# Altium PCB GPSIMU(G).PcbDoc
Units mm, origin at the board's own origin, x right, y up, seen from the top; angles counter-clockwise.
Board outline 35 x 59.99 mm, 2 copper layers (Top Layer, Bottom Layer); 106 components, 112 nets, 390 pads, 86 vias.
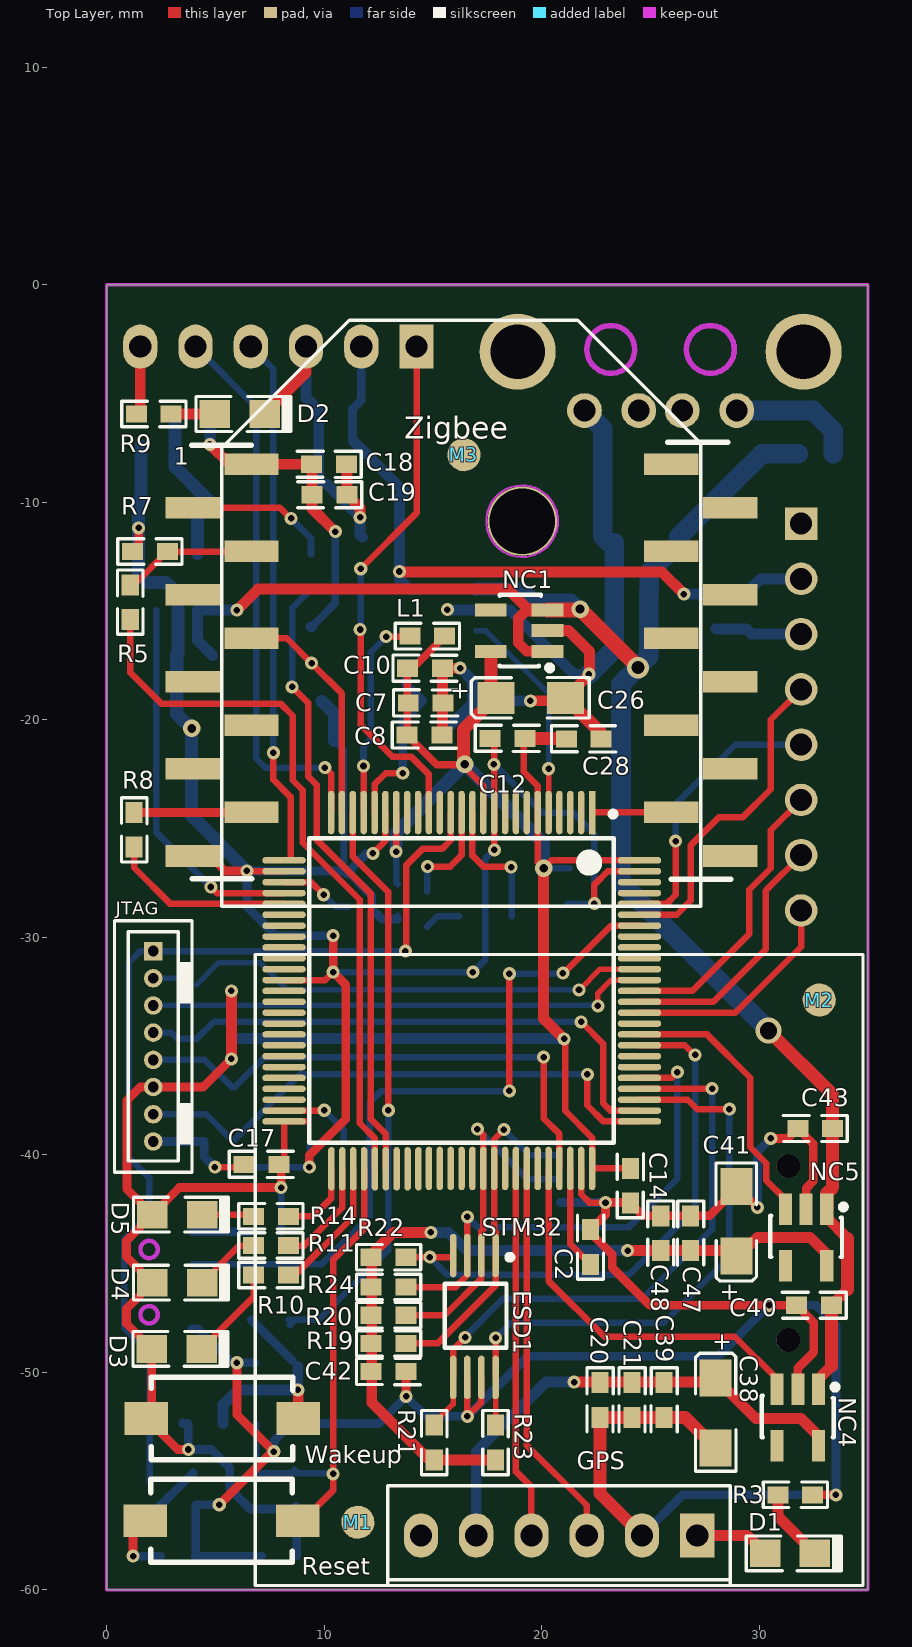
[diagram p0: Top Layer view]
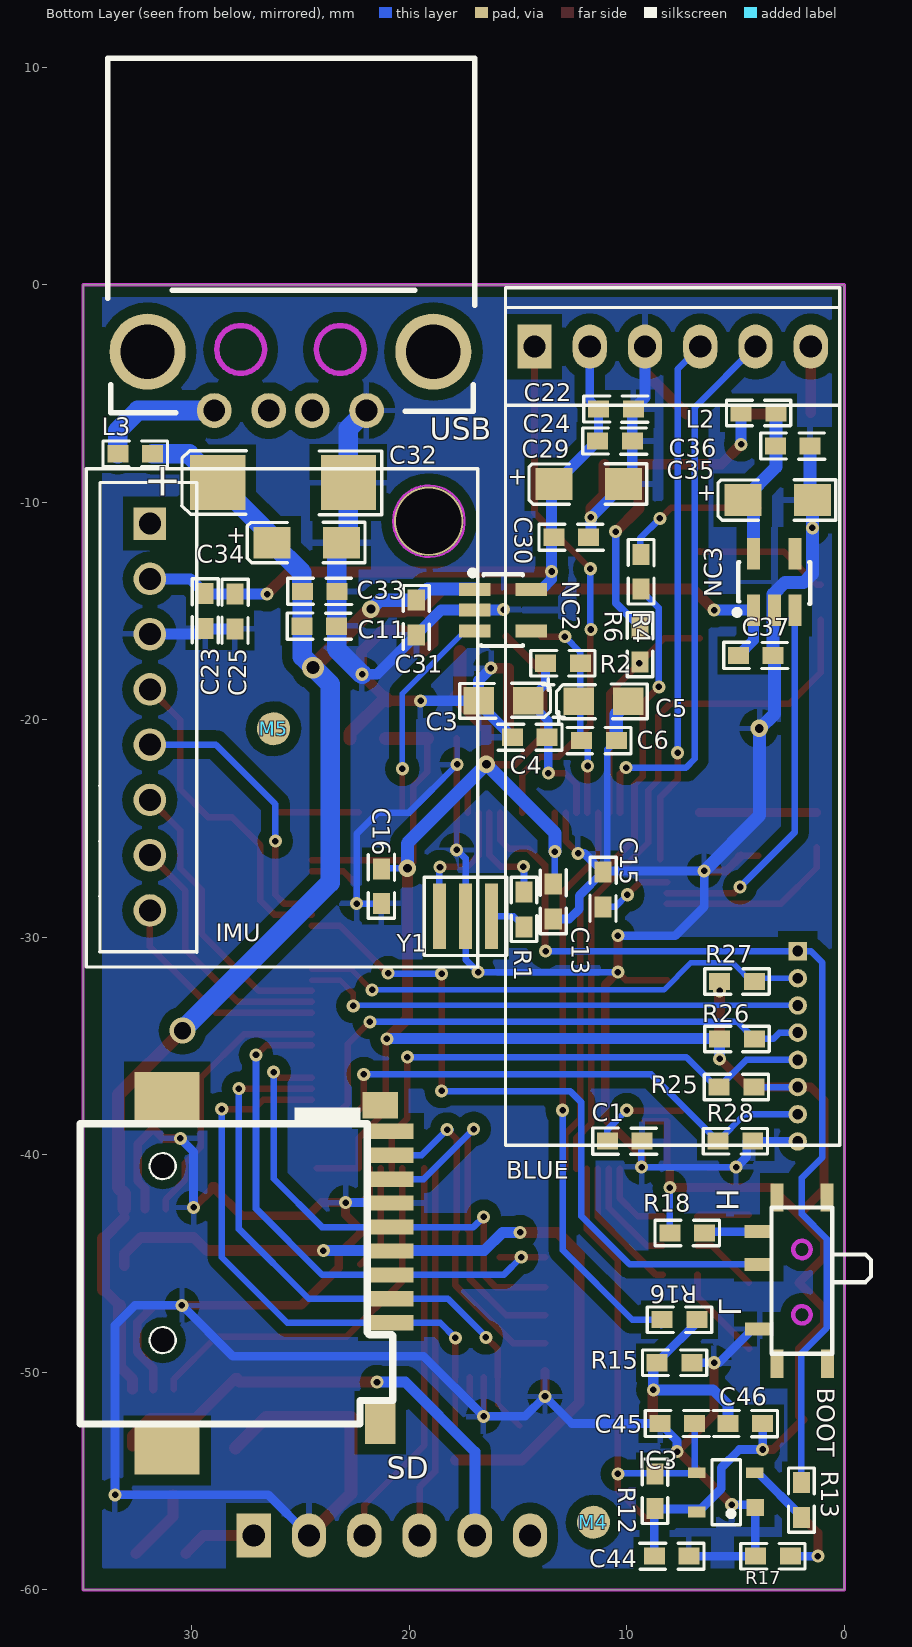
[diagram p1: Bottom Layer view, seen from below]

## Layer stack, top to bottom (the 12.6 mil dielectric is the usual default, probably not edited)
Top Layer: signal copper 0.0356
Dielectric: core 0.32, FR-4, Dk 4.8
Bottom Layer: signal copper 0.0356

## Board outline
0,0 35.001,0 35.001,-59.995 0,-59.995

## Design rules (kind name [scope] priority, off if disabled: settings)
Clearance [All] p1: gap=0.5
PolygonConnect [All] p1: connectstyle=Relief reliefconductorwidth=0.254 reliefentries=4 polygonreliefangle="90 Angle"
RoutingVias [All] p1: holewidth=0.711 width=1.27 viastyle="Through Hole" minholewidth=0.711 minwidth=1.27 maxholewidth=0.711 maxwidth=1.27
SilkscreenOverComponentPads [All] p1: minsilkscreentomaskgap=0.254
SolderMaskExpansion [All] p1: expansion=0.102
Width [All] p1: maxlimit=2.54 minlimit=0.2 preferedwidth=0.254
27 further rules are at their usual default settings.

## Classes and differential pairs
component class CPU_STM32F4: C1 C2 C3 C4 C5 C6 C7 C8 C10 C12 C13 C14 C15 C16 C17 L1 R1 R2 STM32 Y1
component class IMU_GPS: BLUE Bluetooth C18 C19 C20 C21 C22 C23 C24 C25 D1 D2 GPS IC2 IMU L2 P1 P2 P3 R3 R4 R5 R6 R7 R8 R9 Zigbee
component class IMU_POW: C11 C26 C27 C28 C29 C30 C31 C32 C33 C34 C35 C36 C37 C38 C39 C40 C41 C42 C43 L3 NC1 NC2 NC3 NC4 NC5
component class IMU_REIO: BOOT C44 C45 C46 D3 D4 D5 IC3 M1 M2 M3 M4 M5 M6 R10 R11 R12 R13 R14 R15 R16 R17 R18 Reset S1 S2 Wakeup
component class IMU_SD: C47 C48 ESD1 J1 JTAG R19 R20 R21 R22 R23 R24 R25 R26 R27 R28 SD

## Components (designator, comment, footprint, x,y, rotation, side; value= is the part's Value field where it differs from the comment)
BLUE "蓝牙模块" HC-06(35.7*15.2MM) 14.249,-2.845 r180 bottom locked (schematic designator P3)
BOOT "SW-SPDT" SW-PD-5(10) 1.829,-49.149 r90 bottom locked (schematic designator S3)
C1 "1uF" 0603 9.296,-39.37 r0 bottom
C2 "1uF" 0603 22.25,-43.434 r270 top
C3 "1uF/16V" C-M(0805) 14.91,-20.269 r0 bottom
C4 "100n" 0603 15.265,-20.803 r180 bottom
C5 "1uF/16V" C-M(0805) 11.836,-18.009 r180 bottom
C6 "100n" 0603 12.09,-20.955 r180 bottom
C7 "100n" 0603 15.469,-19.228 r180 top
C8 "100n" 0603 15.418,-20.701 r180 top
C10 "100n" 0603 15.443,-17.628 r180 top
C11 "100n" 0603 23.343,-15.697 r0 bottom
C12 "100n" 0603 19.228,-20.853 r180 top
C13 "100n" 0603 13.386,-27.559 r270 bottom
C14 "100n" 0603 24.079,-40.615 r270 top
C15 "100n" 0603 11.1,-28.6 r90 bottom
C16 "100n" 0603 21.285,-26.848 r270 bottom
C17 "100n" 0603 7.925,-40.437 r180 top
C18 "100n" 0603 9.423,-8.255 r0 top
C19 "100n" 0603 9.449,-9.652 r0 top
C20 "100n" 0603 22.682,-52.07 r90 top
C21 "100n" 0603 24.155,-52.07 r90 top
C22 "100n" 0603 9.703,-5.715 r0 bottom
C23 "100n" 0603 29.388,-15.799 r90 bottom
C24 "100n" 0603 9.754,-7.188 r0 bottom
C25 "100n" 0603 28.016,-15.824 r90 bottom
C26 "4u7/10V" C-A(3216-18) 17.907,-18.999 r0 top
C28 "100n" 0603 22.733,-20.879 r180 top
C29 "4u7/10V" C-A(3216-18) 13.36,-9.169 r180 bottom
C30 "100n" 0603 11.76,-11.608 r0 bottom
C31 "100n" 0603 19.685,-16.104 r90 bottom
C32 "220u/10V" C-C(6032-28) 28.804,-9.093 r180 bottom
C33 "100n" 0603 23.317,-14.097 r0 bottom
C34 "4u7/10V" C-A(3216-18) 26.314,-11.862 r180 bottom
C35 "4u7/10V" C-A(3216-18) 4.674,-9.906 r180 bottom
C36 "100n" 0603 1.575,-7.417 r0 bottom
C37 "100n" 0603 3.277,-17.043 r0 bottom
C38 "4u7/10V" C-A(3216-18) 27.991,-50.267 r270 top
C39 "100n" 0603 25.629,-52.07 r90 top
C40 "100n" 0603 31.725,-46.914 r0 top
C41 "4u7/10V" C-A(3216-18) 28.956,-44.653 r90 top
C42 "100n" 0603 13.767,-49.962 r180 top
C43 "100n" 0603 31.775,-38.786 r0 top
C44 "100n" 0603 8.738,-58.445 r180 bottom
C45 "100n" 0603 6.883,-52.349 r0 bottom
C46 "100n" 0603 5.359,-52.349 r180 bottom
C47 "100n" 0603 26.848,-44.399 r90 top
C48 "100n" 0603 25.476,-44.399 r90 top
D1 "LED red" D0805 30.277,-58.318 r0 top
D2 "LED red" D0805 4.978,-5.944 r0 top
D3 "LED red" D0805 2.083,-48.92 r0 top
D4 "LED red" D0805 2.108,-45.872 r0 top
D5 "LED red" D0805 2.108,-42.748 r0 top
ESD1 "PESD5V0L6UAS" MSOP-8 17.882,-44.628 r270 top
GPS "GPS" "GPS 28*28MM" 27.635,-48.565 r270 top locked (schematic designator P1)
IC3 "MAX6315US26D2-T" TO-253 4.877,-54.991 r0 top
IMU "IMU" GY-85 24.232,-18.567 r180 bottom locked (schematic designator P2)
JTAG "CON-SIP8-2.0" PLUG1.27-8P 2.261,-33.477 r270 top (schematic designator P4)
L1 "22uH" 0603 15.545,-16.154 r180 top
L2 "22uH" 0603 3.15,-5.893 r0 bottom
L3 "22uH" 0603 33.401,-7.772 r180 bottom
M1 "CON-PAD" BAD_MARK 11.557,-56.871 r0 top
M2 "CON-PAD" BAD_MARK 32.766,-32.868 r0 top
M3 "CON-PAD" BAD_MARK 16.434,-7.798 r0 top
M4 "CON-PAD" BAD_MARK 11.532,-56.871 r180 bottom
M5 "CON-PAD" BAD_MARK 26.238,-20.396 r180 bottom
NC1 "NCP603SN330T1G" TSSOP-5 19.406,-16.256 r180 top
NC2 "NCP603SN330T1G" TSSOP-5 16.129,-14.605 r180 bottom
NC3 "NCP603SN330T1G" TSSOP-5 3.581,-14.097 r90 bottom
NC4 "NCP603SN330T1G" TSSOP-5 32.131,-51.638 r270 top
NC5 "NCP603SN330T1G" TSSOP-5 32.512,-43.358 r270 top
R1 "390" 0603 14.732,-29.515 r90 bottom
R2 "47" 0603 12.141,-17.399 r0 bottom
R3 "1K" 0603 32.461,-55.626 r180 top
R4 "1K" 0603 9.347,-12.395 r270 bottom
R5 "10K" 0603 1.092,-13.792 r270 top
R6 "10K" 0603 9.398,-15.748 r270 bottom
R7 "15K" 0603 2.794,-12.268 r180 top
R8 "1K" 0603 1.27,-24.257 r270 top
R9 "1K" 0603 2.972,-5.944 r180 top
R10 "1K" 0603 6.756,-45.517 r0 top
R11 "1K" 0603 6.756,-44.171 r0 top
R12 "47K" 0603 8.712,-54.661 r270 bottom
R13 "3.9K" 0603 1.981,-56.667 r90 bottom
R14 "1K" 0603 6.756,-42.824 r0 top
R15 "47K" 0603 7.01,-49.555 r0 bottom
R16 "1K" 0603 6.782,-47.574 r0 bottom
R17 "10K" 0603 4.089,-58.445 r180 bottom
R18 "10K" 0603 6.426,-43.586 r0 bottom
R19 "10K" 0603 13.767,-48.666 r180 top
R20 "10K" 0603 13.767,-47.371 r180 top
R21 "10K" 0603 15.062,-52.426 r270 top
R22 "10K" 0603 13.767,-44.704 r180 top
R23 "10K" 0603 17.882,-52.426 r270 top
R24 "10K" 0603 13.767,-46.076 r180 top
R25 "3.9K" 0603 5.766,-36.881 r180 bottom
R26 "3.9K" 0603 4.14,-34.671 r0 bottom
R27 "3.9K" 0603 4.14,-32.029 r0 bottom
R28 "3.9K" 0603 4.216,-39.37 r0 bottom
Reset "Manual Pushbutton" KEY-6*4 1.778,-56.82 r90 top locked (schematic designator S1)
SD "SD_CARD_SLOT" mini-SD 21.641,-46.076 r0 bottom locked (schematic designator J1)
STM32 "STM32F40x-VG (LQFP100)" "LQFP100 (14*14)" 17.602,-31.013 r270 top locked (schematic designator IC1)
USB "车载转换头" SMT-USB 18.898,-3.073 r0 bottom (schematic designator J(USB)2)
Wakeup "Manual Pushbutton" KEY-6*4 8.814,-52.121 r270 top locked (schematic designator S2)
Y1 "8Mhz" XT-3.2*1.5 18.618,-29.032 r180 bottom
Zigbee "XBEE PRO(802.15.4)/" SMT-Zigbee-2.0 3.962,-8.255 r0 top locked (schematic designator IC2)

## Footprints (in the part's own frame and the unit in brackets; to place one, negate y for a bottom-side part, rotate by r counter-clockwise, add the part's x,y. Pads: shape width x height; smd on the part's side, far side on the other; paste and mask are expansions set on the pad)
0603 [mil]
  rect 38x31 smd: 1(0,0) 2(63,0)
  silkscreen extent -26,-24 90,24
BAD_MARK [mil] "MARK 点"
  round 60 smd mask+29.53: 0(-0.25,-0.63)
C-A(3216-18) [mm]
  rect 1.7x1.47 smd: 1(0,0) 2(3.2,0)
  silkscreen extent -1.14,-0.92 4.28,0.94
C-C(6032-28) [mm]
  rect 2.54x2.54 smd: 1(0,0) 2(6,0)
  silkscreen extent -1.66,-1.47 7.53,1.45
C-M(0805) [mil] "钽电容"
  rect 55.12x50 smd: 1(-15,-45) 2(75,-45)
  silkscreen extent -80,-76 109,-5
D0805 [mm]
  rect 1.4x1.27 smd: A(0,0) K(2.286,0)
  silkscreen extent -0.87,-0.81 3.5,0.8
"GPS 28*28MM" [mil] "BS-280  GPS接收"
  rect 80x62 hole 40: 1(351.73,-19)
  oval 80x62 hole 40: 2(351.73,-119) 3(351.73,-219) 4(351.73,-319) 5(351.73,-419) 6(351.73,-519)
  silkscreen extent -700,-819 442,281
GY-85 [mm]
  round 3.2 hole 3: 0(5.12,7.698)
  rect 1.5x1.5 hole 1.016: 1(-7.697,7.584)
  round 1.5 hole 1.016: 2(-7.697,5.044) 3(-7.697,2.504) 4(-7.697,-0.036) 5(-7.697,-2.576) 6(-7.697,-5.116) 7(-7.697,-7.656) 8(-7.697,-10.196)
  silkscreen extent -10.63,-12.8 7.37,10.11
HC-06(35.7*15.2MM) [mil] "蓝牙模块"
  rect 62x80 hole 40: 1(0,0)
  oval 62x80 hole 40: 2(100,0) 3(200,0) 4(300,0) 5(400,0) 6(500,0)
  silkscreen extent -52,-1446 552,106
KEY-6*4 [mm] "2PIN"
  rect 1.5x2 smd: 1(0,0) 2(0,-7)
  silkscreen extent -1.9,-6.75 1.9,-0.25
"LQFP100 (14*14)" [mm]
  rect 2x0.3 smd: 1(-6.751,4.716)
  oval 2x0.3 smd: 2(-6.751,4.216) 3(-6.751,3.716) 4(-6.751,3.216) 5(-6.751,2.716) 6(-6.751,2.216) 7(-6.751,1.716) 8(-6.751,1.216) 9(-6.751,0.716) 10(-6.751,0.216) 11(-6.751,-0.284) 12(-6.751,-0.784) 13(-6.751,-1.284) 14(-6.751,-1.784) 15(-6.751,-2.284) 16(-6.751,-2.784) 17(-6.751,-3.284) 18(-6.751,-3.784) 19(-6.751,-4.284) 20(-6.751,-4.784) 21(-6.751,-5.284) 22(-6.751,-5.784) 23(-6.751,-6.284) 24(-6.751,-6.784) 25(-6.751,-7.284) 51(9.629,-7.264) 52(9.629,-6.764) 53(9.629,-6.264) 54(9.629,-5.764) 55(9.629,-5.264) 56(9.629,-4.764) 57(9.629,-4.264) 58(9.629,-3.764) 59(9.629,-3.264) 60(9.609,-2.784) 61(9.609,-2.284) 62(9.609,-1.784) 63(9.609,-1.284) 64(9.609,-0.784) 65(9.609,-0.284) 66(9.609,0.216) 67(9.609,0.716) 68(9.609,1.216) 69(9.609,1.716) 70(9.609,2.216) 71(9.609,2.716) 72(9.609,3.216) 73(9.609,3.716) 74(9.609,4.216) 75(9.609,4.716)
  oval 0.3x2 smd: 26(-4.551,-9.444) 27(-4.051,-9.444) 28(-3.551,-9.444) 29(-3.051,-9.444) 30(-2.551,-9.444) 31(-2.051,-9.444) 32(-1.551,-9.444) 33(-1.051,-9.444) 34(-0.551,-9.444) 35(-0.051,-9.444) 36(0.449,-9.444) 37(0.949,-9.444) 38(1.449,-9.444) 39(1.949,-9.444) 40(2.449,-9.444) 41(2.949,-9.444) 42(3.449,-9.444) 43(3.949,-9.444) 44(4.449,-9.444) 45(4.949,-9.444) 46(5.449,-9.444) 47(5.949,-9.444) 48(6.449,-9.444) 49(6.949,-9.444) 50(7.449,-9.444) 76(7.449,6.896) 77(6.949,6.896) 78(6.449,6.896) 79(5.949,6.896) 80(5.449,6.896) 81(4.949,6.896) 82(4.449,6.896) 83(3.949,6.896) 84(3.449,6.896) 85(2.949,6.896) 86(2.449,6.896) 87(1.949,6.896) 88(1.449,6.896) 89(0.949,6.896) 90(0.449,6.896) 91(-0.051,6.896) 92(-0.551,6.896) 93(-1.051,6.896) 94(-1.551,6.896) 95(-2.051,6.896) 96(-2.551,6.896) 97(-3.051,6.896) 98(-3.551,6.896) 99(-4.051,6.896) 100(-4.551,6.896)
  silkscreen extent -6.8,-8.28 8.43,5.8
mini-SD [mm]
  rect 1.629x1.225 smd: 0(-0.301,-8.358)
  rect 1.4x1.93 smd: 0(-0.301,6.242)
  rect 3x2.2 smd: 0(9.5,-8.778) 0(9.5,7.52)
  rect 2.057x0.7 smd: 1(-0.801,1.642) 2(-0.801,0.542) 3(-0.801,-0.558) 4(-0.801,-1.658) 5(-0.801,-2.758) 6(-0.801,-3.858) 7(-0.801,-4.958) 8(-0.801,-6.058) 9(-0.801,-7.158)
  round 1.1 hole 1.1: ""(9.699,-5.558) ""(9.699,2.442)
  silkscreen extent -0.88,-8.26 13.5,6.29
MSOP-8 [mm]
  oval 2x0.3 smd: 1(0,0) 2(0,-0.65) 3(0,-1.3) 4(0,-1.95) 5(5.6,-1.95) 6(5.6,-1.3) 7(5.6,-0.65) 8(5.6,0)
  silkscreen extent -0.05,-2.34 4.24,0.79
PLUG1.27-8P [mm]
  rect 0.85x0.85 hole 0.5: 1(-2.845,-0.114)
  round 0.85 hole 0.5: 2(-1.595,-0.114) 3(-0.345,-0.114) 4(0.905,-0.114) 5(2.155,-0.114) 6(3.405,-0.114) 7(4.655,-0.114) 8(5.905,-0.114)
  silkscreen extent -4.24,-1.89 7.32,1.66
SMT-USB [mm]
  round 3.5 hole 2.5: 0(0,0) 0(13.14,0)
  round 1.6 hole 1: 1(3.07,2.71) 2(5.57,2.71) 3(7.57,2.71) 4(10.07,2.71)
  Keep-Out Layer circle w0.254: c4.28,-0.1 r1.1
  Keep-Out Layer circle w0.254: c8.86,-0.1 r1.1
  silkscreen extent -1.89,-13.49 14.97,2.81
SMT-Zigbee-2.0 [mm] "2.0MM"
  rect 2.5x1 smd: 1(2.7,0) 2(0,-2) 3(2.7,-4) 4(0,-6) 5(2.7,-8) 6(0,-10) 7(2.7,-12) 8(0,-14) 9(2.7,-16) 10(0,-18) 11(24.7,-18) 12(22,-16) 13(24.7,-14) 14(22,-12) 15(24.7,-10) 16(22,-8) 17(24.7,-6) 18(22,-4) 19(24.7,-2) 20(22,0)
  silkscreen extent -0.05,-20.32 24.74,6.63
SW-PD-5(10) [mm]
  rect 1.3x0.6 smd: 0(-0.457,-1.041) 0(-0.457,1.27) 0(7.188,-1.016) 0(7.188,1.27)
  rect 0.6x1.3 smd: 1(1.143,2.083) 2(4.118,2.108) 3(5.618,2.108)
  Keep-Out Layer circle w0.2: c4.8,0.127 r0.4
  Keep-Out Layer circle w0.2: c1.8,0.127 r0.4
  silkscreen extent 0,-3.05 6.73,1.52
TO-253 [mm]
  rect 0.8x0.8 smd far side: 1(-0.781,-1.219)
  rect 0.8x0.5 smd far side: 2(-0.761,0.381) 3(1.919,0.381) 4(1.919,-1.419)
TSSOP-5 [mm]
  rect 1.45x0.6 smd: 1(-0.864,0.595) 2(-0.864,-0.355) 3(-0.864,-1.305) 4(1.736,-1.305) 5(1.736,0.595)
  silkscreen extent -1.09,-2 1.34,1.48
XT-3.2*1.5 [mm] "3.2*1.3*0.4mm"
  rect 0.6x3 smd: 1(0,0) 2(1.2,0) 3(2.4,0)
  silkscreen extent -0.7,-1.8 3.1,1.8

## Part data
BLUE: library part CON-SIP6-2.54, "单排针6PIN"
BOOT: "SPDT Subminiature Toggle Switch, Right Angle Mounting, Vertical Actuation"
C1 C2 C4 C6 C7 C8 C10 C11 C12 C13 C14 C15 C16 C17 C44 C45 C46: library part Cap, "TANTAMOUNT? 595D Vishay Sprague,50V,22.5mOhm"
C3 C5 C26 C29 C34 C35 C38 C41: library part C-A(3216-18)
C18 C19 C47 C48: library part Cap, "Capacitor"
C20 C21 C22 C23 C24 C25 C28 C31 C37 C40 C43: library part C-SMD
C30 C36 C39 C42: library part "Cap Semi", "Capacitor (Semiconductor SIM Model)"
C32: library part C-RB.1
C33: library part C-SMD电容
D1 D2 D3 D4 D5: library part diode-LED, "LED"
ESD1: library part PESD5V0L6U
GPS: library part CON6-2.54, "(栅)围栏式立(卧)6PIN"
IC3: library part "MAX 6468", "MAX 6468XS16D3 Reset and Supervisory Circuit"
IMU: library part CON8-2.54, "(栅)围栏式立(卧)8PIN"
JTAG: "单排针8PIN"
L1: library part Inductor, "fcm1608-0603"
L2: library part L-
L3: library part INDUCTOR
NC1 NC2 NC3 NC4 NC5: library part NCP551
R1 R2 R4 R5 R6 R7 R8 R10 R11 R12 R13 R14 R15 R16 R17 R18 R19 R20 R21 R22 R23 R24: library part Res3, "Resistor"
R3 R9: library part R-0603, "0603(SMD)"
R25 R26 R27 R28: library part R-0805, "0805(SMD)"
Reset Wakeup: library part 微动开关
STM32: library part STM32F40x-VG
USB: library part CON-USB1, "USB"
Y1: library part CRYSTAL-X3, "3PIN"
Zigbee: library part "XBEE PRO(802.15.4)"

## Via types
v1: diameter 0.6, hole 0.3, Top Layer to Bottom Layer, 80 vias
v2: diameter 0.8, hole 0.4, Top Layer to Bottom Layer, 4 vias
v3: diameter 1.2, hole 0.8, Top Layer to Bottom Layer, 1 vias
v4: diameter 1, hole 0.6, Top Layer to Bottom Layer, 1 vias

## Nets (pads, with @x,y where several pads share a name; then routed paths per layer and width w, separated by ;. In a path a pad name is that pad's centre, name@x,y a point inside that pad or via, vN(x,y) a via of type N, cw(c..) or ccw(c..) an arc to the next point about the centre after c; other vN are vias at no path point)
"BOOT0 (VPP)": BOOT.2 STM32.94 | length 34.8
  Top Layer w0.3: v1@18.517,-37.084 v1(18.517,-37.059) v1(18.517,-31.674) ; v1@20.98,-31.674 23.192,-29.462 STM32.94
  Bottom Layer w0.3: BOOT.2 7.569,-45.031 ; 8.613,-45.031 7.569,-45.031 ; 13.945,-37.084 13.437,-37.084 ; v1@18.491,-31.674 v1(18.517,-31.674) v1@20.98,-31.674 ; v1(18.517,-37.059) 18.491,-37.084 13.437,-37.084 ; 7.569,-45.031 9.881,-45.031 12.09,-42.822 12.09,-37.592 12.598,-37.084 13.437,-37.084
  other v1: 20.98,-31.648
CAR_5V: C11.2 C31.2 C32.1 C33.2 C34.1 C37.2 C40.2 C43.2 L3.2 NC1.1 NC1.3 NC2.1 NC3.1 NC4.1 NC5.1 | length 85.1
  Top Layer w0.5: v1(5.994,-14.961) 6.96,-13.995 18.452,-13.995 19.314,-14.857 19.314,-14.951 18.923,-15.342 18.923,-16.459 19.315,-16.851 NC1.1 ; NC4.1 32.726,-50.307 33.325,-49.708 ; NC5.1@33.107,-42.886 34.061,-43.84 ; C40.2 34.061,-46.177
  Top Layer w0.6: 19.314,-14.951 NC1.3 ; v3(30.429,-34.29) 33.376,-37.236 C43.2 33.376,-41.504 33.107,-41.772 NC5.1 ; 33.325,-49.708 C40.2 ; 34.061,-46.177 34.061,-43.84
  Top Layer w0.7: NC1.3 21.809,-14.951 v4@24.473,-17.615
  Bottom Layer w0.5: C37.2 4.176,-16.343 NC3.1 v1(5.994,-14.961) ; NC2.1@16.916,-13.995 NC2.1@17.008,-13.995
  Bottom Layer w0.6: NC2.1 17.008,-13.995 19.177,-13.995 C31.2 21.361,-14.503 v2(21.768,-14.91)
  Bottom Layer w0.9: C33.2 24.917,-17.094 23.647,-18.364 23.647,-27.483 v3@30.442,-34.277 ; C33.2@24.943,-14.097 24.943,-13.233 C34.1 26.314,-11.582 C32.1 30.124,-7.772 L3.2
  other v4: 24.435,-17.602
GND: BLUE.3 BOOT.1 C1.1 C2.1 C3.2 C4.1 C5.2 C6.2 C7.1 C8.1 C10.1 C11.1 C12.2 C13.2 C14.2 C15.2 C16.2 C17.2 C18.2 C19.2 C20.1 C21.1 C22.1 C23.1 C24.1 C25.1 C26.2 C28.1 C29.2 C30.1 C31.1 C32.2 C33.1 C34.2 C35.2 C36.1 C37.1 C38.2 C39.1 C40.1 C41.2 C42.1 C43.1 C44.2 C45.2 C47.2 C48.2 D2.K ESD1.6 ESD1.7 GPS.2 IC3.1 IMU.3 JTAG.8 NC1.2 NC2.2 NC3.2 NC4.2 NC5.2 R3.1 R7.2 R15.1 R17.1 R28.1 SD.6 STM32.10 STM32.20 STM32.27 STM32.37 STM32.74 STM32.99 USB.1 Y1.2 Zigbee.10 | length 294.1
  Top Layer w0.3: Zigbee.10 4.75,-26.255 Zigbee.10@4.894,-26.255 ; v1(4.978,-40.564) C17.2@6.248,-40.564 ; v1@6.452,-26.962 STM32.27 ; STM32.37 10.049,-31.962 v1(10.414,-31.598) ; v1(12.243,-26.137) 12.818,-25.561 STM32.20 ; v1@16.582,-52.024 v1(16.586,-52.019) 17.232,-51.374 ESD1.7 ; v1@16.582,-52.019 ESD1.6 ; C12.2@17.818,-20.853 STM32.10 17.818,-25.972 v1(17.831,-25.984) ; STM32.74 21.818,-41.808 22.199,-42.189 v1@22.885,-42.189 ; v1(22.428,-28.448) 22.428,-27.572 23.038,-26.962 STM32.99
  Top Layer w0.4: R7.2@1.473,-12.268 v1(1.473,-11.176) ; Zigbee.10@4.75,-26.255 5.444,-26.949 v1(6.452,-26.949) ; v1(5.182,-56.083) 7.62,-53.645 v1(7.696,-53.645) 5.994,-51.943 v1(5.994,-49.555) ; v1(9.322,-40.564) 9.322,-40.031 10.998,-38.355 10.998,-32.182 v1(10.414,-31.598) v1(10.414,-29.921) ; v1@13.767,-51.079 C42.1 ; v1@22.885,-42.189 v1(22.936,-42.189) ; C14.2@24.054,-42.189 v1(22.936,-42.189) ; C14.2 24.663,-42.799 C48.2 C47.2 27.712,-42.799 C41.2@29.007,-41.504 ; C41.2 C41.2@29.007,-41.504 ; C41.2@29.058,-41.453 C41.2@29.007,-41.504 ; v1(29.921,-42.418) C41.2@29.007,-41.504 ; v1(30.455,-46.914) 24.968,-46.914 23.241,-45.187 23.241,-44.583 22.25,-43.592 C2.1 22.936,-42.748 v1(22.936,-42.189) ; v1@30.48,-46.914 C40.1 32.512,-47.701 32.512,-49.073 31.776,-49.809 NC4.2 ; v1(30.531,-39.243) 31.318,-39.243 C43.1 32.487,-39.497 32.487,-41.199 32.157,-41.528 NC5.2 ; R3.1 v1(33.528,-55.626) v1@33.579,-55.626
  Top Layer w0.5: D2.K 9.169,-4.039 BLUE.3 ; C18.2 11.049,-8.28 C19.2 11.659,-10.262 v1(11.659,-10.693) ; C8.1@15.443,-20.676 C10.1 v1(16.256,-17.628) ; v1(19.482,-19.126) C26.2@20.98,-19.126 ; NC1.2@20.313,-15.944 NC1.2 21.235,-15.901 22.2,-16.866 v1@22.2,-17.907 ; C26.2 v1@22.199,-17.907 ; v1(22.174,-17.907) v1@22.199,-17.907
  Top Layer w0.6: C26.2@20.98,-19.126 C26.2 22.733,-20.625 C28.1 ; GPS.2 22.682,-55.568 C20.1 C21.1 C39.1 26.594,-52.07 C38.2
  Bottom Layer w0.3: v1(4.978,-40.564) v1(9.322,-40.564) ; v1@9.347,-40.513 C1.1@9.347,-39.37 ; v1(10.414,-31.598) 16.789,-31.598 16.815,-31.623 v1(16.84,-31.598) 17.418,-31.02 Y1.2 17.418,-26.371 v1@17.831,-25.959 ; C6.2 10.897,-21.361 10.897,-26.797 11.049,-26.949 C15.2 ; C13.2 C13.2@13.386,-29.007 ; v1@17.755,-21.996 v1(17.805,-22.047) 20.041,-24.282 21.463,-24.282 22.428,-25.248 v1(22.428,-28.448) C16.2 C16.2@21.184,-28.448
  Bottom Layer w0.4: JTAG.8@2.134,-39.382 4.216,-39.382 R28.1 ; BOOT.1 4.216,-48.006 5.766,-49.555 v1(5.994,-49.555) R15.1@6.833,-49.555 ; R28.1@4.242,-39.382 4.496,-39.382 4.496,-40.081 v1(4.978,-40.564) ; v1(5.182,-56.083) 4.096,-56.083 4.096,-58.439 R17.1 C44.2 ; v1@7.696,-53.518 7.696,-53.137 C45.2 12.522,-52.349 v1(13.767,-51.105) 14.681,-52.019 v1(16.586,-52.019) 19.355,-49.251 28.118,-49.251 v1(30.455,-46.914) 32.614,-46.914 33.528,-47.828 v1(33.528,-55.626) 26.485,-55.626 GPS.2 ; v1(10.414,-29.921) 7.772,-29.921 6.452,-28.6 v1(6.452,-26.949) C15.2@11.049,-26.949 ; v1(12.243,-26.137) 11.963,-26.137 C15.2 12.192,-28.092 12.192,-28.702 12.649,-29.159 C13.2 ; SD.6@20.858,-42.189 v1@22.885,-42.189 ; v1(29.921,-42.418) 29.921,-39.853 v1(30.531,-39.243)
  Bottom Layer w0.5: BLUE.3 9.169,-5.182 C22.1 9.754,-5.766 C24.1 C29.2@9.754,-9.093 ; C29.2 10.16,-9.195 v1(11.659,-10.693) 11.659,-11.506 C30.1 ; C4.1 16.815,-19.253 C3.2 ; v1@15.672,-14.96 NC2.2 18.541,-14.96 C31.1 21.488,-17.907 v1(22.174,-17.907) ; v1(16.256,-17.628) 16.815,-18.186 16.815,-18.999 16.942,-19.126 v1(19.482,-19.126) ; C25.1 29.413,-15.824 29.653,-16.064 IMU.3
  Bottom Layer w0.6: C36.1 1.575,-9.805 C35.2 1.474,-13.259 1.476,-13.262 1.476,-13.293 1.874,-13.691 2.738,-13.691 3.277,-14.229 C37.1 3.226,-16.993 3.226,-19.736 v2@3.912,-20.422 ; v2(3.912,-20.396) v2@3.912,-20.422 ; v2@3.937,-20.447 v2@3.912,-20.422 ; v1(6.452,-26.949) 3.912,-24.409 v2@3.912,-20.422 ; C5.2@9.906,-19.152 10.49,-19.736 C6.2 ; C15.2 C15.2@11.159,-27
  Bottom Layer w0.9: USB.1 22.804,-6.619 C32.2 22.804,-11.551 C34.2 ; v1(22.174,-17.907) 23.343,-16.739 C11.1 C34.2@23.343,-11.862
  other v1: 15.672,-14.935
NetC18_1: C18.1 C19.1 L2.2 R6.1 Zigbee.1 | length 14.8
  Top Layer w0.5: v1(4.75,-7.341) 5.664,-8.255 Zigbee.1 C18.1 ; C18.1@9.449,-8.28 C19.1 9.449,-10.287 v1(10.516,-11.354)
  Bottom Layer w0.3: R6.1 R6.1@9.423,-15.723
  Bottom Layer w0.35: R6.1@9.423,-15.723 10.516,-14.63 v1@10.516,-11.405
  Bottom Layer w0.5: v1@4.75,-7.315 L2.2 ; R6.1@9.398,-15.723 R6.1@9.423,-15.723
NetC46_1: C46.1 R15.2 R16.1 Wakeup.1 | length 9.7
  Top Layer w0.5: Wakeup.1@8.814,-52.273 v1@8.814,-50.876
  Bottom Layer w0.4: R16.1@6.655,-47.574 R15.2@8.522,-49.441
  Bottom Layer w0.5: C46.1 5.359,-51.486 6.045,-50.8 v1(8.788,-50.8) R15.2@8.788,-49.733
NetD1_A: D1.A GPS.1 | length 3.5
  Top Layer w0.5: GPS.1 29.457,-57.499 D1.A
NetD1_K: D1.K R3.2 | length 3.4
  Top Layer w0.5: R3.2 30.861,-56.617 D1.K
NetD2_A: D2.A R9.1 | length 1.7
  Top Layer w0.5: R9.1 D2.A@4.699,-5.944
NetD3_K: D3.K R10.1 | length 4.4
  Top Layer w0.3: D3.K 6.756,-46.533 R10.1
NetD4_K: D4.K R11.1 | length 3.1
  Top Layer w0.3: D4.K 6.096,-44.171 R11.1
NetD5_K: D5.K R14.1 | length 2.4
  Top Layer w0.3: D5.K 6.68,-42.748 R14.1
NetIC2_2: R4.1 Zigbee.2 | length 6.9
  Top Layer w0.254: Zigbee.2 Zigbee.2@4.08,-10.373 ; v1@8.471,-10.757 v1@8.496,-10.782
  Top Layer w0.3: Zigbee.2 7.969,-10.255 v1@8.471,-10.757
  Bottom Layer w0.3: v1(8.484,-10.744) 9.398,-11.659 R4.1@9.398,-12.395
NetIC2_3: R5.1 R7.1 Zigbee.3 | length 6.2
  Top Layer w0.3: R5.1 1.27,-13.792 R7.1 6.649,-12.268 Zigbee.3
NetIC2_9: R8.1 Zigbee.9 | length 6.4
  Top Layer w0.4: R8.1 3.861,-24.257 ; 2.819,-24.257 3.861,-24.257 ; Zigbee.9 6.66,-24.257 3.861,-24.257
NetIC3_2: IC3.2 R13.1 | length 2.9
  Bottom Layer w0.4: R13.1 1.981,-56.618 IC3.2@3.976,-54.623
NetJ(USB)2_4: L3.1 USB.4 | length 5.9
  Bottom Layer w0.9: USB.4 32.479,-5.783 33.401,-6.706 L3.1
NetP3_6: BLUE.6 R9.2 | length 3
  Top Layer w0.5: R9.2@1.549,-5.867 BLUE.6
NetR1_1: R1.1 Y1.3 | length 1.7
  Bottom Layer w0.3: R1.1 15.215,-29.032 Y1.3
NetR17_2: R17.2 Reset.1 | length 3.1
  Top Layer w0.4: v1(1.219,-58.445) 1.219,-57.379 Reset.1
  Bottom Layer w0.4: v1@1.245,-58.445 R17.2
NetR18_1: BOOT.3 R18.1 | length 2.7
  Bottom Layer w0.4: BOOT.3 6.583,-43.531 R18.1@6.604,-43.51
NRST: JTAG.1 R13.2 STM32.14 | length 45.9
  Top Layer w0.3: v1@13.767,-30.607 13.767,-26.695 14.529,-25.933 15.418,-25.933 15.818,-25.533 STM32.14
  Bottom Layer w0.3: R13.2 1.981,-49.124 0.813,-47.955 0.813,-43.866 1.956,-42.723 1.956,-41.046 1.016,-40.107 1.016,-31.166 1.549,-30.632 v1(13.741,-30.632)
PA0: R16.2 STM32.23 | length 28.8
  Top Layer w0.3: STM32.23 11.318,-26.279 12.954,-27.915 12.954,-32.004 ; v1@12.954,-37.973 v1(12.954,-37.948) 12.954,-32.004 ; 12.954,-33.934 12.954,-32.004
  Bottom Layer w0.3: R16.2 9.754,-47.574 12.954,-44.374 v1@12.954,-37.973 ; R16.2@8.433,-47.828 R16.2@8.534,-47.727
PA1: R6.2 STM32.24 Zigbee.5 | length 10.7
  Top Layer w0.3: Zigbee.5 8.279,-16.255 v1(9.423,-17.399) 10.818,-18.794 STM32.24
PA2: BLUE.5 STM32.25 | length 25.6
  Top Layer w0.3: v1(10.033,-22.2) 10.318,-22.485 STM32.25
  Bottom Layer w0.3: BLUE.5 6.883,-5.639 6.883,-21.793 7.29,-22.2 v1(10.033,-22.2)
PA3: BLUE.4 STM32.26 | length 24.4
  Top Layer w0.3: v1@7.671,-21.488 7.671,-22.758 8.458,-23.546 STM32.26@8.458,-26.407
  Bottom Layer w0.3: BLUE.4 7.671,-3.886 v1@7.671,-21.539
  other v1: 7.671,-21.514
PA4: NC3.3 STM32.29 | length 17.3
  Top Layer w0.3: v1(4.801,-27.686) 5.077,-27.962 STM32.29
  Bottom Layer w0.2: v1(4.801,-27.686) v1@4.877,-27.686
  Bottom Layer w0.3: NC3.3 2.276,-25.162 v1(4.801,-27.686)
PA5: R8.2 STM32.30 | length 8.5
  Top Layer w0.3: R8.2 1.27,-26.797 2.935,-28.462 STM32.30
PA6: STM32.31
PA7: STM32.32
PA8: STM32.67
PA9: GPS.4 STM32.68 | length 17.2
  Top Layer w0.3: STM32.68 18.818,-54.556 19.533,-55.27 GPS.4
PA10: GPS.3 STM32.69 | length 18
  Top Layer w0.3: STM32.69 19.318,-53.354 22.073,-56.109 GPS.3
PA11: STM32.70
PA12: NC4.3 STM32.71 | length 18
  Top Layer w0.3: STM32.71 20.318,-45.794 22.885,-48.362 28.88,-48.362 30.826,-50.308 NC4.3
PA13: JTAG.5 R25.1 STM32.72 | length 24.9
  Top Layer w0.254: STM32.72@20.818,-41.023 STM32.72
  Top Layer w0.3: v1(20.091,-35.509) 20.091,-38.313 20.818,-39.04 STM32.72
  Bottom Layer w0.254: R25.1 R25.1@5.893,-36.881
  Bottom Layer w0.3: JTAG.5@2.134,-35.632 4.517,-35.632 R25.1 ; R25.1@5.893,-36.881 7.264,-35.509 v1(20.091,-35.509)
PA14: JTAG.7 R28.2 STM32.76 | length 26.1
  Top Layer w0.254: v1(22.098,-36.297) v1@22.098,-36.246
  Top Layer w0.3: v1(22.098,-36.297) 22.098,-37.719 22.841,-38.462 STM32.76
  Bottom Layer w0.254: R28.2@5.715,-39.37 R28.2 ; v1@22.098,-36.271 v1@22.123,-36.271
  Bottom Layer w0.3: JTAG.7@2.134,-38.132 4.579,-38.132 R28.2 8.89,-36.297 v1(22.098,-36.297)
PA15: JTAG.4 R26.1 STM32.77 | length 26.2
  Top Layer w0.254: v1@21.793,-33.884 v1(21.819,-33.884) ; STM32.77@24.475,-37.939 STM32.77
  Top Layer w0.3: v1(21.819,-33.884) 22.835,-34.9 22.835,-37.635 23.162,-37.962 STM32.77
  Bottom Layer w0.3: JTAG.4@2.134,-34.382 2.988,-34.382 3.277,-34.671 R26.1 4.928,-33.884 v1(21.819,-33.884)
PB0: STM32.35
PB1: STM32.36
PB3: JTAG.3 STM32.89 | length 23.2
  Top Layer w0.254: v1(22.581,-33.147) 22.581,-32.572 23.19,-31.962 STM32.89
  Bottom Layer w0.254: JTAG.3@2.134,-33.132 v1@22.566,-33.132
PB4: JTAG.2 R27.1 STM32.90 | length 23.4
  Top Layer w0.254: v1@21.742,-32.436 21.742,-32.41 22.69,-31.462 STM32.90
  Bottom Layer w0.254: JTAG.2@2.134,-31.882 R27.1@3.841,-31.882 ; R27.1@4.14,-32.182 5.156,-31.166 7.061,-31.166 8.306,-32.41 v1(21.717,-32.41)
PB5: STM32.91
PB6: STM32.92
PB7: STM32.93
PB8: IMU.4 STM32.95 | length 15.1
  Top Layer w0.254: STM32.95 STM32.95@24.521,-28.939
  Top Layer w0.3: STM32.95 26.206,-28.962 26.848,-28.321 26.848,-25.781 28.143,-24.486 29.235,-24.486 30.531,-23.19 30.531,-20.001 IMU.4
PB9: IMU.5 STM32.96 | length 12.9
  Top Layer w0.3: STM32.96 25.741,-28.462 26.162,-28.042 v1(26.162,-25.578)
  Bottom Layer w0.3: v1(26.162,-25.578) 26.162,-23.876 28.894,-21.144 IMU.5
PB10: STM32.47
PB11: STM32.48
PB12: R14.2 STM32.51 | length 3.7
  Top Layer w0.3: R14.2 9.5,-42.824 10.338,-41.986 STM32.51
PB13: R11.2 STM32.52 | length 5
  Top Layer w0.3: R11.2 9.093,-44.171 10.838,-42.426 STM32.52
PB14: R10.2 STM32.53 | length 6.3
  Top Layer w0.3: R10.2 8.661,-45.517 11.338,-42.84 STM32.53
PB15: C45.1 IC3.3 R12.1 Reset.2 STM32.54 | length 23.6
  Top Layer w0.3: Reset.2 9.017,-56.82 10.414,-55.423 10.414,-44.831 11.838,-43.407 STM32.54
  Bottom Layer w0.3: IC3.3@6.858,-54.635 R12.1@8.697,-54.635 ; IC3.3@6.883,-54.585 C45.1 ; R12.1@8.636,-54.483 8.788,-54.635 10.338,-54.635 10.414,-54.559 v1@10.439,-54.559
  other v1: 10.414,-54.661
PC0: STM32.15
PC1: BLUE.1 STM32.16 | length 25.7
  Top Layer w0.3: v1@11.684,-15.824 11.684,-20.244 13.132,-21.692 13.995,-21.692 14.818,-22.514 STM32.16 ; v1(11.684,-13.056) 14.249,-10.49 BLUE.1
  Bottom Layer w0.3: v1@11.684,-15.85 v1(11.684,-13.056) 11.684,-14.478
  other v1: 11.659,-15.85
PC2: STM32.17
PC3: STM32.18
PC4: STM32.33
PC5: STM32.34
PC6: STM32.63
PC7: STM32.64
PC8: ESD1.2 R20.1 SD.7 STM32.65 | length 16
  Top Layer w0.254: STM32.65@17.295,-40.645 STM32.65
  Top Layer w0.3: R20.1 15.545,-47.371 17.232,-45.684 ESD1.2 17.232,-43.521 17.318,-43.434 STM32.65 17.318,-39.086 v1(17.043,-38.811)
  Bottom Layer w0.3: v1(17.043,-38.811) 19.35,-41.117 SD.7
PC9: ESD1.1 R19.1 SD.8 STM32.66 | length 15.8
  Top Layer w0.3: R19.1 15.215,-48.666 17.882,-45.999 ESD1.1 17.882,-43.561 17.818,-43.498 STM32.66 17.818,-39.281 v1(18.263,-38.837)
  Bottom Layer w0.254: v1@18.085,-38.837 v1@18.174,-38.925
  Bottom Layer w0.3: v1(18.263,-38.837) 19.443,-40.017 SD.8
PC10: ESD1.8 R23.1 SD.1 STM32.78 | length 27.4
  Top Layer w0.254: R23.1 ESD1.8
  Top Layer w0.3: ESD1.8 v1(17.882,-48.412) ; STM32.78 26.718,-37.462 27.153,-37.897 v1(28.626,-37.897)
  Bottom Layer w0.254: v1@17.882,-48.463 v1@17.907,-48.438
  Bottom Layer w0.3: v1(17.882,-48.412) 18.577,-47.717 SD.1 25.612,-47.717 28.626,-44.704 v1(28.626,-37.897)
PC11: ESD1.5 R21.1 SD.2 STM32.79 | length 28
  Top Layer w0.254: R21.1@14.935,-52.451 15.932,-51.455 ESD1.5
  Top Layer w0.3: ESD1.5 15.932,-48.94 v1(16.485,-48.387) ; STM32.79 v1@27.838,-36.962
  Bottom Layer w0.254: v1@16.434,-48.412 v1@16.472,-48.374
  Bottom Layer w0.3: v1@16.472,-48.374 18.229,-46.617 SD.2 24.63,-46.617 27.838,-43.409 v1(27.838,-36.957)
PC12: ESD1.3 R24.1 SD.5 STM32.80 | length 23.2
  Top Layer w0.254: v1@16.582,-42.854 v1(16.586,-42.85)
  Top Layer w0.3: R24.1 16.041,-46.076 16.582,-45.535 ESD1.3 v1@16.582,-42.854 ; STM32.80 25.971,-36.462 v1(26.238,-36.195)
  Bottom Layer w0.3: v1(16.586,-42.85) 17.054,-43.317 SD.5 24.018,-43.317 26.238,-41.097 26.238,-38.049 v1(26.238,-36.195)
PC13: STM32.7
PC14: STM32.8
PC15: STM32.9
PD0: STM32.81
PD1: STM32.82
PD2: ESD1.4 R22.1 SD.3 STM32.83 | length 25.7
  Top Layer w0.254: v1@27.038,-35.42 v1@27.051,-35.433
  Top Layer w0.3: R22.1 v1(14.859,-44.704) ESD1.4@15.855,-44.704 ; STM32.83 26.58,-34.962 v1@27.038,-35.42
  Bottom Layer w0.254: v1(27.051,-35.408) v1@27.051,-35.382
  Bottom Layer w0.3: v1(14.859,-44.704) 15.672,-45.517 SD.3 24.002,-45.517 27.051,-42.469 v1(27.051,-35.408)
PD3: NC5.3 STM32.84 | length 12.6
  Top Layer w0.3: STM32.84 27.604,-34.462 29.591,-36.449 29.591,-39.649 30.328,-40.386 30.328,-41.173 31.207,-42.053 NC5.3
PD4: STM32.85
PD5: IMU.8 STM32.86 | length 10.4
  Top Layer w0.3: STM32.86 28.895,-33.462 31.929,-30.428 IMU.8
PD6: IMU.7 STM32.87 | length 11.8
  Top Layer w0.3: STM32.87 27.896,-32.962 30.302,-30.556 30.302,-27.85 IMU.7
PD7: IMU.6 STM32.88 | length 13.3
  Top Layer w0.3: STM32.88 26.923,-32.462 29.54,-29.845 29.54,-27.813 30.531,-26.822 30.531,-25.081 IMU.6
PD8: R5.2 STM32.55 | length 33.1
  Top Layer w0.3: R5.2 1.092,-17.831 2.515,-19.253 8.001,-19.253 8.56,-19.812 8.56,-22.779 9.017,-23.236 9.017,-25.654 11.636,-28.273 11.636,-38.541 12.338,-39.244 STM32.55
PD9: R4.2 STM32.56 | length 28.8
  Top Layer w0.3: v1@8.509,-18.466 v1(8.534,-18.491) 9.271,-19.228 9.271,-22.606 9.652,-22.987 9.652,-25.502 12.136,-27.985 12.136,-38.334 12.838,-39.037 STM32.56
  Bottom Layer w0.3: v1(8.534,-18.491) 8.534,-14.859 R4.2@9.398,-13.995
PD10: STM32.57
PD11: STM32.58
PD12: STM32.59
PD13: STM32.60
PD14: STM32.61
PD15: STM32.62
PE0: STM32.97
PE1: STM32.98
PE2: STM32.1 Zigbee.12 | length 3.6
  Top Layer w0.254: STM32.1 STM32.1@22.326,-24.255
  Top Layer w0.3: STM32.1@22.326,-24.255 Zigbee.12
PE3: STM32.2
PE4: STM32.3
PE5: STM32.4
PE6: NC2.3 STM32.5 | length 10
  Top Layer w0.254: STM32.5 v1@20.318,-22.252
  Bottom Layer w0.254: NC2.3 17.434,-15.91 20.32,-18.796 v1@20.32,-22.276
  other v1: 20.32,-22.25
PE7: STM32.38
PE8: STM32.39
PE9: STM32.40
PE10: STM32.41
PE11: STM32.42
PE12: STM32.43
PE13: STM32.44
PE14: STM32.45
PE15: STM32.46
"PH0-OSC_IN (OSC_IN)": STM32.12 Y1.1 | length 7.1
  Top Layer w0.3: STM32.12 16.818,-26.242 17.323,-26.746 18.618,-26.746 17.755,-26.746
  Bottom Layer w0.3: Y1.1 v1@18.618,-26.772
  other v1: 18.593,-26.772
"PH1-OSC_OUT (OSC_OUT)": R1.2 STM32.13 | length 5.6
  Top Layer w0.3: 15.519,-26.746 v1(14.757,-26.746) 15.799,-26.746 16.318,-26.227 STM32.13
  Bottom Layer w0.3: R1.2 v1@14.732,-26.772
VBAT: C7.2 C8.2 C10.2 C12.1 C13.1 C14.1 C16.1 C17.1 C26.1 C28.2 C44.1 C46.2 D3.A D4.A D5.A IC3.4 JTAG.6 L1.1 NC1.5 R12.2 R18.2 R25.2 R26.2 R27.2 STM32.6 STM32.11 STM32.19 STM32.50 STM32.75 STM32.100 Wakeup.2 | length 131.8
  Top Layer w0.3: C17.1@8.158,-40.467 STM32.50 9.202,-38.462 ; v1@13.318,-26.06 STM32.19 ; C10.2 C10.2@14.072,-17.628 ; v2@16.396,-22.111 17.318,-23.033 STM32.11 ; C12.1@19.177,-20.853 19.177,-22.403 19.818,-23.044 STM32.6 19.818,-26.549 v2(20.091,-26.822) 20.451,-26.462 STM32.100 ; v1@21.082,-34.925 21.082,-37.973 22.318,-39.209 STM32.75 C14.1@24.249,-40.622
  Top Layer w0.35: L1.1 13.818,-17.882 C8.2 15.189,-22.073 v2@16.358,-22.073
  Top Layer w0.4: v1(3.759,-53.543) 3.277,-53.543 1.91,-52.177 2.083,-52.004 D3.A 0.914,-47.752 0.914,-47.066 D4.A 0.914,-44.679 0.914,-43.942 D5.A ; v1(5.74,-35.585) 4.443,-36.882 2.134,-36.882 1.548,-36.882 0.94,-37.49 0.94,-41.58 D5.A ; C17.1@8.158,-40.467 8.026,-40.599 v1(8.026,-41.504) 3.353,-41.504 D5.A
  Top Layer w0.5: v1(5.74,-35.585) v1(5.74,-32.461) ; v2(20.091,-26.822) 20.091,-33.731 v1(21.031,-34.671) ; C28.2@21.107,-20.853 C28.2
  Top Layer w0.6: v2@16.4,-22.03 16.4,-20.446 17.848,-18.999 C26.1 17.67,-18.762 NC1.5 ; C12.1@19.177,-20.853 C28.2@21.107,-20.853
  Bottom Layer w0.3: JTAG.6@2.134,-36.882 4.164,-36.882 R25.2 ; R18.2 v1(8.026,-41.504) v1@8.026,-41.478 ; v1(13.31,-26.06) 13.31,-27.483 C13.1 ; v2(20.091,-26.822) C16.1@21.285,-26.822
  Bottom Layer w0.4: C46.2@3.505,-52.349 C46.2@3.505,-52.324 ; v1@3.759,-53.569 v1(3.759,-53.543) ; C46.2 v1(3.759,-53.543) ; R12.2@8.64,-56.283 6.6,-56.283 5.664,-55.347 5.664,-54.381 4.826,-53.543 v1(3.759,-53.543) ; R12.2@8.712,-56.159 8.738,-56.185 C44.1
  Bottom Layer w0.5: v1@5.74,-35.611 v1(5.74,-35.585) R26.2 ; R26.2@5.74,-34.646 v1@21.031,-34.646
  Bottom Layer w0.6: v1(13.31,-26.06) 13.31,-25.197 v2(16.459,-22.047) 20.091,-25.679 v2(20.091,-26.822)
VCAP_1: C1.2 STM32.49 | length 4.4
  Top Layer w0.3: STM32.49@7.472,-37.962 STM32.49 v1@10.033,-37.962
  Bottom Layer w0.3: v1(10.008,-37.948) 10.058,-37.998 10.897,-38.837 C1.2
VCAP_2: C2.2 STM32.73 | length 4.8
  Top Layer w0.3: STM32.73 21.318,-44.102 C2.2
VDD4: C15.1 STM32.28 | length 3.4
  Top Layer w0.254: v1(9.982,-28.042) v1@9.995,-28.054
  Top Layer w0.3: STM32.28 9.403,-27.462 v1(9.982,-28.042)
  Bottom Layer w0.3: v1(9.982,-28.042) 10.541,-28.6 C15.1
VDD_DEVICE: BLUE.2 C22.2 C23.2 C24.2 C25.2 C29.1 C30.2 IMU.2 NC2.5 | length 34.1
  Top Layer w0.5: v1@13.414,-13.205 18.136,-13.205 ; 16.329,-13.205 18.136,-13.205 ; v1(26.543,-14.224) 25.524,-13.205 18.136,-13.205
  Bottom Layer w0.4: C24.2 11.303,-7.137 C22.2 11.709,-5.309 BLUE.2
  Bottom Layer w0.5: C24.2 13.665,-9.5 13.665,-9.576 13.462,-9.779 13.462,-12.09 13.462,-13.538 13.934,-14.01 NC2.5 ; v1@26.518,-14.224 v1(26.543,-14.224) C25.2 29.362,-14.224 C23.2 30.063,-13.524 IMU.2
  other v1: 13.462,-13.183
VDD_GPS: C20.2 C21.2 C38.1 C39.2 GPS.5 NC4.5 | length 22.8
  Top Layer w0.5: v1(21.488,-50.444) 24.155,-50.444 27.813,-50.444 C38.1 ; C38.1@27.864,-50.394 C38.1 ; C38.1@27.915,-50.267 C38.1 ; NC4.5 32.726,-52.919 31.928,-52.121 29.845,-52.121 C38.1
  Bottom Layer w0.5: GPS.5 16.993,-53.645 20.193,-50.444 v1(21.488,-50.444)
VDD_SD: C41.1 C42.2 C47.1 C48.1 NC5.5 R19.2 R20.2 R21.2 R22.2 R23.2 R24.2 SD.4 | length 36.6
  Top Layer w0.5: R22.2 12.167,-44.577 R22.2@12.192,-44.552 ; v1(14.91,-43.561) 13.183,-43.561 R22.2@12.192,-44.552 ; R23.2 14.834,-54.026 12.192,-51.384 12.192,-48.666 12.192,-46.076 R22.2@12.192,-44.552 ; v1(23.952,-44.399) C48.1 25.654,-44.399 26.924,-44.399 29.312,-44.399 29.35,-44.361 29.921,-43.79 32.334,-43.79 33.107,-44.562 NC5.5
  Bottom Layer w0.5: v1(14.91,-43.561) 15.723,-43.561 16.561,-44.399 20.84,-44.399 v1(23.952,-44.399)
VDDA: C5.1 C6.1 L1.2 R2.1 STM32.22 | length 9.7
  Top Layer w0.3: v1@11.786,-22.124 11.786,-22.098 v1(11.811,-22.123) 11.818,-22.131 STM32.22 ; v1(12.852,-16.18) L1.2@13.945,-16.18
  Bottom Layer w0.3: v1@11.836,-22.123 11.811,-22.098 11.811,-21.234 C6.1 12.141,-20.904 R2.1 12.141,-16.891 v1(12.852,-16.18)
VREF+: C3.1 C4.2 R2.2 STM32.21 | length 8.5
  Top Layer w0.3: STM32.21 12.318,-22.968 12.832,-22.454 v1(13.614,-22.454)
  Bottom Layer w0.4: v1@13.614,-22.428 13.614,-20.041 C3.1 13.741,-18.339 R2.2
ZIGBEE_VDD: C35.1 C36.2 L2.1 NC3.5 | length 7.3
  Bottom Layer w0.6: L2.1 3.15,-8.382 C35.1 4.176,-10.403 NC3.5
pads on no net: BOOT.0 GPS.6 IMU.0 IMU.1 M1.0 M2.0 M3.0 M4.0 M5.0 NC1.4 NC2.4 NC3.4 NC4.4 NC5.4 SD. SD.0 SD.9 USB.0 USB.2 USB.3 Zigbee.4 Zigbee.6 Zigbee.7 Zigbee.8 Zigbee.11 Zigbee.13 Zigbee.14 Zigbee.15 Zigbee.16 Zigbee.17 Zigbee.18 Zigbee.19 Zigbee.20

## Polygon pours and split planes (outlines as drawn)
GND on Bottom Layer "Bottom Layer-No Net" (solid, remove dead copper, pour order 1000): 0.434,-0.16 0.535,-0.262 34.114,-0.262 34.114,-58.961 34.063,-59.012 0.307,-59.012

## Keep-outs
Keep-Out Layer:
  circle w0.1: c19.104,-10.871 r1.648
  lines w0.152: 0,-60 35,-60 35,0 0,0 0,-60

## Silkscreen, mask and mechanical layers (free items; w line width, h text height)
Bottom Overlay:
  text "H" at 5.867,-42.596 h1 r90
  text "L" at 5.766,-47.422 h1 r90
